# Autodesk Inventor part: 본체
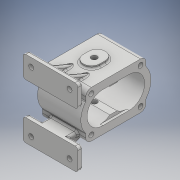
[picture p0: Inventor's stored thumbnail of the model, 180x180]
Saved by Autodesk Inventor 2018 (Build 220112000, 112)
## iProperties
Created: 2023-06
Part Number: 본체
Material: 일반
Document SubType Name: Modeling
Designer: home
Density: 1 g/cm^3
Appearance: 기본값
Author: home
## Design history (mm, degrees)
sketch "스케치1"
  geometry: L1 (-45, 70)-(45, 70); L2 (50, 65)-(50, 35); L3 (45, 30)-(-45, 30); L4 (-50, 35)-(-50, 65); L5 (-50, 70)-(50, 30); L6 (50, 70)-(-50, 30); L7 (-45, -30)-(45, -30); L8 (50, -35)-(50, -65); L9 (45, -70)-(-45, -70); L10 (-50, -65)-(-50, -35); L11 (-50, -30)-(50, -70); L12 (50, -30)-(-50, -70); A1 r 5 centre (45, 65) between (50, 65) and (45, 70); A2 r 5 centre (45, 35) between (45, 30) and (50, 35); A3 r 5 centre (-45, 35) between (-50, 35) and (-45, 30); A4 r 5 centre (-45, 65) between (-45, 70) and (-50, 65); A5 r 5 centre (-45, -35) between (-45, -30) and (-50, -35); A6 r 5 centre (-45, -65) between (-50, -65) and (-45, -70); A7 r 5 centre (45, -65) between (45, -70) and (50, -65); A8 r 5 centre (45, -35) between (50, -35) and (45, -30); 5 further points
  constraints: 24 end point, 16 point on circle, 16 point on line, 16 tangent, 8 centre point, 7 equal radius, 6 midpoint, 4 parallel, 2 horizontal, 2 perpendicular, 2 vertical alignment
  dimensions: "d0" = 100 distance of L5.end L6.end; "d1" = 40 distance of L6.start L5.end; "d2" = 100 distance of L11.end L12.end; "d3" = 40 distance of L12.start L11.end; "d6" = 5 radius of A1; "d35" = 140 distance between parallel lines of L9 L1; "d37" = 70 distance from line of point (0, 0) L1
extrude "돌출1" new body sketch "스케치1" distance "d7" = 9; taper "d8" = 0 deg
sketch "스케치2"
  geometry: L1 (35, 42.5)-(125, 42.5); L2 (135, 32.5)-(135, -32.5); L3 (125, -42.5)-(35, -42.5); L4 (25, -32.5)-(25, 32.5); L5 (25, 42.5)-(135, -42.5); L6 (135, 42.5)-(25, -42.5); L7 (86.507, -22.5)-(73.493, -22.5); L8 (86.507, 22.5)-(73.493, 22.5); A1 r 28.5 centre (104, 0) between (86.507, -22.5) and (86.507, 22.5); A2 r 28.5 centre (56, 0) between (73.493, 22.5) and (73.493, -22.5); A3 r 40 centre (56, 0) between (25, 25.278) and (25, -25.278); A4 r 40 centre (104, 0) between (135, -25.278) and (135, 25.278); A5 r 10 centre (125, 32.5) between (135, 32.5) and (125, 42.5); A6 r 10 centre (125, -32.5) between (125, -42.5) and (135, -32.5); A7 r 10 centre (35, -32.5) between (25, -32.5) and (35, -42.5); A8 r 10 centre (35, 32.5) between (35, 42.5) and (25, 32.5); 4 further points
  constraints: 16 end point, 16 point on circle, 12 point on line, 8 centre point, 8 tangent, 4 midpoint, 3 equal radius, 3 horizontal, 3 horizontal alignment, 2 coincident, 2 parallel, 1 perpendicular
  dimensions: "d9" = 110 distance of L5.end L6.end; "d10" = 85 distance of L6.start L5.end; "d11" = 80 distance of point (0, 0) point (80, 0); "d12" = 28.5 radius of A1; "d14" = 24 distance of A1.centre point (80, 0); "d15" = 24 distance of point (80, 0) A2.centre; "d16" = 22.5 distance from line of L7 point (80, 0); "d17" = 22.5 distance from line of L8 point (80, 0); "d18" = 28.5 radius of A2; "d19" = 40 radius of A3; "d20" = 40 radius of A4; "d21" = 10 radius of A5
extrude "돌출2" join sketch "스케치2" stored distance "d22" = 79; taper "d23" = 0 deg
sketch "스케치3"
  geometry: L1 (-22.5, 73.493)-(-22.5, 86.507) reference; L2 (22.5, 86.507)-(22.5, 73.493) reference; L3 (25.278, 25)-(32.5, 25) reference; L4 (42.5, 35)-(42.5, 125) reference; L5 (32.5, 135)-(25.278, 135) reference; L6 (-25.278, 135)-(-32.5, 135) reference; L7 (-42.5, 125)-(-42.5, 35) reference; L8 (-32.5, 25)-(-25.278, 25) reference; A1 r 28.5 centre (0, 56) between (-22.5, 73.493) and (22.5, 73.493) reference; A2 r 28.5 centre (0, 104) between (22.5, 86.507) and (-22.5, 86.507) reference; A3 r 40 centre (0, 56) between (-25.278, 25) and (25.278, 25) reference; A4 r 10 centre (32.5, 35) between (32.5, 25) and (42.5, 35) reference; A5 r 10 centre (32.5, 125) between (42.5, 125) and (32.5, 135) reference; A6 r 40 centre (0, 104) between (25.278, 135) and (-25.278, 135) reference; A7 r 10 centre (-32.5, 125) between (-32.5, 135) and (-42.5, 125) reference; A8 r 10 centre (-32.5, 35) between (-42.5, 35) and (-32.5, 25) reference; 5 further points
  constraints: 4 coincident
hole "구멍1" sketch "스케치3" at (-32.5, 125), (32.5, 125), (32.5, 35), (-32.5, 35) diameter "d24" = 9; stored, may be unused: countersink angle "d28" = 90 deg, drill point angle "d30" = 118 deg; dims "d25" = 6, "d26" = 4, "d27" = 2, "d29" = 8
sketch "스케치4"
  geometry: L1 (-50, -65)-(-50, -35) reference; L2 (-45, -30)-(45, -30) reference; L3 (50, -35)-(50, -65) reference; L4 (45, -70)-(-45, -70) reference; L5 (50, 35)-(50, 65) reference; L6 (-45, 30)-(45, 30) reference; L7 (-50, 65)-(-50, 35) reference; L8 (45, 70)-(-45, 70) reference; L9 (-25, -34)-(25, -34); L10 (-21, -38)-(21, -38); L11 (21, -30)-(-21, -30); L12 (-25, 34)-(25, 34); L13 (-21, 30)-(21, 30); L14 (21, 38)-(-21, 38); A1 r 5 centre (-45, -35) between (-45, -30) and (-50, -35) reference; A2 r 5 centre (45, -35) between (50, -35) and (45, -30) reference; A3 r 5 centre (45, -65) between (45, -70) and (50, -65) reference; A4 r 5 centre (-45, -65) between (-50, -65) and (-45, -70) reference; A5 r 5 centre (45, 35) between (45, 30) and (50, 35) reference; A6 r 5 centre (-45, 35) between (-50, 35) and (-45, 30) reference; A7 r 5 centre (-45, 65) between (-45, 70) and (-50, 65) reference; A8 r 5 centre (45, 65) between (50, 65) and (45, 70) reference; A9 r 4 centre (-21, -34) between (-21, -30) and (-21, -38); A10 r 4 centre (21, -34) between (21, -38) and (21, -30); A11 r 4 centre (-21, 34) between (-21, 38) and (-21, 30); A12 r 4 centre (21, 34) between (21, 30) and (21, 38); 3 further points
  constraints: 16 end point, 12 point on circle, 8 tangent, 4 centre point, 4 point on line, 3 parallel, 2 collinear, 2 midpoint, 2 vertical alignment, 1 horizontal
  dimensions: "d31" = 50 distance of L9.start L9.end; "d32" = 4 radius of A10; "d33" = 50 distance of L12.start L12.end; "d34" = 4 radius of A12
extrude "돌출3" join sketch "스케치4" stored distance "d38" = 79; taper "d39" = 0 deg
node "작업 평면1"
sketch "스케치5"
  geometry: L1 (35, 42.5)-(125, 42.5) reference; L2 (9, 35)-(9, 65) reference; L3 (9, 62)-(54.939, 42.5); L4 (0, 70)-(9, 70) reference; 1 further point
  constraints: 2 end point, 2 point on line
  dimensions: "d41" = 23 deg angle of L3 L4; "d42" = 8 distance from line of L4 L3.start
feature "리브1" sketch "스케치5" dims "d43" = 1, "d44" = 7, "d45" = 0, "d46" = 0, "d47" = 1, "d48" = 1
sketch "스케치6"
  geometry: L1 (-45, 30)-(45, 30) reference; L2 (-50, 65)-(-50, 35) reference; L3 (45, 70)-(-45, 70) reference; L4 (50, 35)-(50, 65) reference; L5 (-45, -30)-(45, -30) reference; L6 (50, -35)-(50, -65) reference; L7 (45, -70)-(-45, -70) reference; L8 (-50, -65)-(-50, -35) reference; C1 r 9 at (35, -55); C2 r 9 at (-35, -55); C3 r 9 at (35, 55); C4 r 9 at (-35, 55); A1 r 5 centre (-45, 35) between (-50, 35) and (-45, 30) reference; A2 r 5 centre (-45, 65) between (-45, 70) and (-50, 65) reference; A3 r 5 centre (45, 65) between (50, 65) and (45, 70) reference; A4 r 5 centre (45, 35) between (45, 30) and (50, 35) reference; A5 r 5 centre (45, -35) between (50, -35) and (45, -30) reference; A6 r 5 centre (45, -65) between (45, -70) and (50, -65) reference; A7 r 5 centre (-45, -65) between (-50, -65) and (-45, -70) reference; A8 r 5 centre (-45, -35) between (-45, -30) and (-50, -35) reference; 1 further point
  constraints: 4 centre point, 1 horizontal, 1 vertical, 6 other
  dimensions: "d49" = 9 radius of C1; "d50" = 55 vertical distance of point (0, 0) C1.centre; "d51" = 35 horizontal distance of point (0, 0) C1.centre; "d54" = 70 distance of C1.centre C2.centre; "d57" = 110 distance of C1.centre C3.centre
extrude "돌출4" join sketch "스케치6" distance "d60" = 3; taper "d61" = 0 deg
sketch "스케치7"
  geometry: C1 r 9 at (-70, 0) reference; C2 r 9 at (0, 0) reference; C3 r 9 at (0, 110) reference; C4 r 9 at (-70, 110) reference; 5 further points
  constraints: 4 coincident
hole "구멍2" sketch "스케치7" at (-70, 0), (0, 0), (0, 110), (-70, 110) diameter "d62" = 9; stored, may be unused: countersink angle "d66" = 90 deg, drill point angle "d68" = 118 deg; dims "d63" = 6, "d64" = 4, "d65" = 2, "d67" = 8
sketch "스케치8"
  geometry: L1 (-28.5, 56)-(28.5, 56); L2 (28.5, 56)-(28.5, 104); L3 (28.5, 104)-(-28.5, 104); L4 (-28.5, 104)-(-28.5, 56); L5 (-28.5, 56)-(28.5, 104); L6 (28.5, 56)-(-28.5, 104); 3 further points
  constraints: 12 end point, 3 midpoint, 2 parallel, 1 horizontal, 1 perpendicular, 1 vertical alignment
  dimensions: "d69" = 57 distance of L3.end L2.end; "d70" = 48 distance of L2.end L1.end; "d71" = 80 distance of point (0, 0) point (0, 80)
extrude "돌출5" cut sketch "스케치8" distance "d72" = 4.5; taper "d73" = 0 deg
sketch "스케치9"
  geometry: L1 (84.5, -125)-(-5.5, -125) reference; L2 (54.5, -40)-(54.5, -50); L3 (24.5, -40)-(24.5, -50); A1 r 15 centre (39.5, -40) between (54.5, -40) and (24.5, -40); A2 r 15 centre (39.5, -50) between (24.5, -50) and (54.5, -50); 2 further points
  constraints: 4 end point, 4 point on circle, 2 centre point, 2 tangent, 2 vertical, 2 vertical alignment, 1 midpoint
  dimensions: "d74" = 15 radius of A1; "d75" = 15 radius of A2; "d76" = 75 distance from line of A2.centre L1; "d77" = 10 distance of A1.centre A2.centre
extrude "돌출6" join sketch "스케치9" distance "d78" = 5; taper "d79" = 0 deg
sketch "스케치10"
  geometry: L1 (84.5, -125)-(-5.5, -125) reference; C1 r 5 at (39.5, -45); 2 further points
  constraints: 1 centre point, 1 midpoint, 1 vertical alignment
  dimensions: "d80" = 5 radius of C1; "d81" = 80 distance from line of L1 C1.centre
extrude "돌출7" cut sketch "스케치10" stored distance "d82" = 5; taper "d83" = 0 deg
node "작업 평면2"
sketch "스케치12"
  geometry: 2 further points
  constraints: 1 horizontal alignment, 1 other
  dimensions: "d95" = 20 distance of point (0, 0) point (-20, 0)
feature "엠보싱1" sketch "스케치12" dims "d0" = 100, "d1" = 40, "d2" = 100, "d3" = 40, "d6" = 5, "d35" = 140, "d37" = 70, "d96" = 0.5, "d97" = 0
fillet "모깎기1" dims "d98" = 3
sketch "스케치13"
  geometry: L1 (-45, -75)-(45, -75) reference; 3 further points
  constraints: 1 midpoint, 1 vertical alignment
  dimensions: "d99" = 80 distance from line of L1 point (0, 5)
hole "구멍4" sketch "스케치13" at (0, 5) diameter "d100" = 10.5; stored, may be unused: countersink angle "d106" = 90 deg, drill point angle "d108" = 118 deg; dims "d101" = 11, "d102" = 0.62479, "d103" = 10.589, "d104" = 4, "d105" = 2, "d107" = 17.5
fillet "모깎기2" dims "d109" = 3
node "솔리드1"
mirror "미러1"
mirror "미러2"
mirror "미러3"
mirror "미러4"
node "투영된 루프1"
node "투영된 루프2"
node "투영된 루프3"
node "투영된 루프4"
node "투영된 루프5"
other parameters: "d13" = 28.5, "d40" = 14.5, "d94" = 144
